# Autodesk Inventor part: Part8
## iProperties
Shininess: 64.0
Length Units: 11269
Angle Units: 11279
Time Units: 11290
Mass Units: 11283
Length Display Precision: 3
Angle Display Precision: 2
Compacted: True
Part Number: Part8
Document SubType Name: Modeling
Created: 2002-12
Designer: deepak
Density: 0.0
Volumn: 0.0
Area: 0.0
PropertySet Name: Model Information
Control State: 0
Master: False
Checked Out: False
Author: deepak
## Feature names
1. Extrusion1
2. Extrusion2
3. Rectangular Pattern1
4. Shell2
5. Split2
